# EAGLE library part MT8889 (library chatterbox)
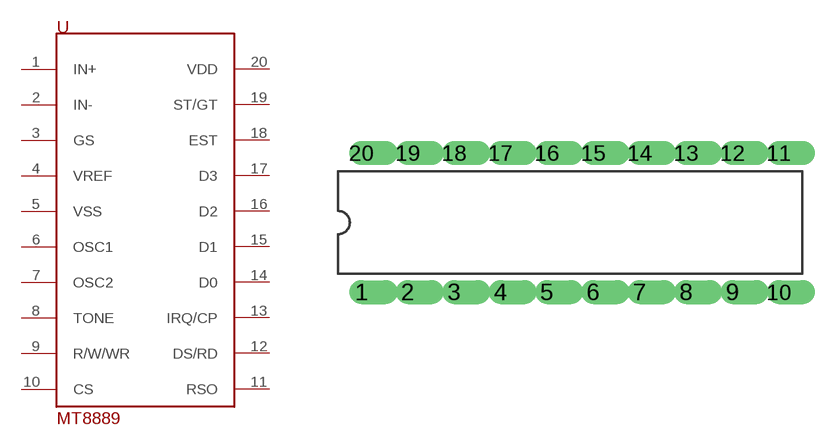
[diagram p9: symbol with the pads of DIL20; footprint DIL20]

Designator prefix -

## MT8889C  [DIL20]
1  IN+
2  IN-
3  GS
4  VREF
5  VSS
6  OSC1
7  OSC2
8  TONE
9  R/W/WR
10  CS
11  RSO
12  DS/RD
13  IRQ/CP
14  D0
15  D1
16  D2
17  D3
18  EST
19  ST/GT
20  VDD

## Footprint DIL20 (pad centres in mm)
DIL
drill 0.813 offset: 1 -11.43,-3.81; 2 -8.89,-3.81; 3 -6.35,-3.81; 4 -3.81,-3.81; 5 -1.27,-3.81; 6 1.27,-3.81; 7 3.81,-3.81; 8 6.35,-3.81; 9 8.89,-3.81; 10 11.43,-3.81; 11 11.43,3.81; 12 8.89,3.81; 13 6.35,3.81; 14 3.81,3.81; 15 1.27,3.81; 16 -1.27,3.81; 17 -3.81,3.81; 18 -6.35,3.81; 19 -8.89,3.81; 20 -11.43,3.81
